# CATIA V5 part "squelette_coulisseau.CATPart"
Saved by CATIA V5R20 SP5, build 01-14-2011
Part number: squelette_coulisseau
Publications: "longueur", "largeur", "hauteur", "Plan.1", "Point.1", "Point.2", "Point.3", "Droite.1", "Plan.3", "Point.4", "Droite.2", "Plan.2"
Bounding box of the stored display mesh (mm): x -15 to 20, y 0 to 200, z -15 to 15
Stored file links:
  F:\iao\catia\projet iao\squelette_coulisseau.CATPart
  F:\iao\catia\projet iao\fhartmann.CATProduct
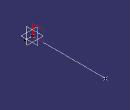
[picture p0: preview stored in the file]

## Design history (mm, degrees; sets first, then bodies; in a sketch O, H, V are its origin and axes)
Parameters
  longueur = 50 mm {= External.coulisseau_longueur}
  largeur = 30 mm {= External.coulisseau_largeur}
  hauteur = 30 mm {= External.coulisseau_hauteur}
External parameters (linked from other documents)
  External.coulisseau_longueur = 50 mm
  External.coulisseau_largeur = 30 mm
  External.coulisseau_hauteur = 30 mm
Set1
  Plane1: type Offset, RefPlane zx-plane, Offset 0
  Point1: type OnPlane, Support Plane1, H 15 {= External.coulisseau_largeur  /2}, V 15 {= External.coulisseau_hauteur  /2}, Direction (-1, 0, 0)
  Point2: type OnPlane, Support Plane1, H -15 {= -External.coulisseau_largeur  /2}, V -15 {= -External.coulisseau_hauteur /2}, Direction (-1, 0, 0)
  Point3: type OnPlane, Support Plane1, H 0, V 0, Direction (-1, 0, 0)
  Plane2: type Offset, RefPlane yz-plane, Offset 0
  Line1: type Normal, RefPoint Point3, RefSkin Plane2, Start 0, End 20
  Plane3: type Offset, RefPlane yz-plane, Offset 15 {= largeur/2}, reversed
  Point4: type OnPlane, Support Plane2, H 200, V 0, Direction (0, 1, 0)
  Line2: type PtPt, FirstPoint Point3, SecondPoint Point4
  Plane4: type Offset, RefPlane Plane2, Offset 15 {= largeur/2}, reversed
Body1 (main body)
